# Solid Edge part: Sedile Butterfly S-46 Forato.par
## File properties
Title: SEDILE BUTTERFLY S-46 FORATA
Author: DESYS
Template: Iso Part.par
Last saved by: PIM_1
Revision: 16
Application: Solid Edge
Tipo di contenuto documento: 0
Accuracy: 0,990
Document Number: 4010
Revision: 0
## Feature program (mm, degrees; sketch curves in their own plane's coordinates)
sketch for "unnamed Protrusion 1" plane through (41.4558, 0, 41.4558) normal (0, 1, 0) x-axis (-1, 0, 0)
extrude "unnamed Protrusion 1" add finite 25 along +normal
sketch for "ScavoEstrusione_1" #1 plane through (180, 25, -217.5) normal (0, 1, 0) x-axis (1, 0, 0)
  line (-60, 177.5) -> (-60, 297.3411)
  line (-190, 297.3411) -> (-60, 297.3411)
  line (-190, 177.5) -> (-190, 297.3411)
  line (-60, 177.5) -> (-190, 177.5)
sketch for "ScavoEstrusione_1" #2 plane through (180, 25, -217.5) normal (0, 1, 0) x-axis (1, 0, 0)
  line (60, 177.5) -> (60, 297.3411)
  line (60, 297.3411) -> (190, 297.3411)
  line (190, 177.5) -> (190, 297.3411)
  line (60, 177.5) -> (190, 177.5)
extrude "ScavoEstrusione_1" cut finite 780 along -normal
sketch for "ScavoEstrusione_2" plane through (180, 25, -217.5) normal (0, 1, 0) x-axis (1, 0, 0)
  line (-75, -157.5) -> (75, -157.5)
  arc centre (75, -107.5) radius 50 from (125, -107.5) to (75, -157.5) cw
  line (125, -107.5) -> (125, 72.5)
  arc centre (75, 72.5) radius 50 from (125, 72.5) to (75, 122.5) ccw
  line (-75, 122.5) -> (75, 122.5)
  arc centre (-75, 72.5) radius 50 from (-75, 122.5) to (-125, 72.5) ccw
  line (-125, 72.5) -> (-125, -107.5)
  arc centre (-75, -107.5) radius 50 from (-75, -157.5) to (-125, -107.5) cw
extrude "ScavoEstrusione_2" cut finite 546 along -normal
sketch for "ScavoEstrusione_3" #1 plane through (180, 25, -217.5) normal (0, 1, 0) x-axis (1, 0, 0)
  arc centre (-75, 72.5) radius 55 from (-75, 127.5) to (-130, 72.5) ccw
  line (-130, 72.5) -> (-130, -107.5)
  arc centre (-75, -107.5) radius 55 from (-130, -107.5) to (-75, -162.5) ccw
  line (-75, -162.5) -> (75, -162.5)
  arc centre (75, -107.5) radius 55 from (75, -162.5) to (130, -107.5) ccw
  line (130, -107.5) -> (130, 72.5)
  arc centre (75, 72.5) radius 55 from (130, 72.5) to (75, 127.5) ccw
  line (75, 127.5) -> (-75, 127.5)
sketch for "ScavoEstrusione_3" #2 plane through (180, 25, -217.5) normal (0, 1, 0) x-axis (1, 0, 0)
  line (-175, 172.5) -> (-45, 172.5)
  line (-45, 172.5) -> (-45, 232.1356)
  line (-45, 232.1356) -> (45, 232.1356)
  line (45, 172.5) -> (45, 232.1356)
  line (175, 172.5) -> (45, 172.5)
  line (175, -212.5) -> (175, 172.5)
  line (-175, -212.5) -> (175, -212.5)
  line (-175, 172.5) -> (-175, -212.5)
extrude "ScavoEstrusione_3" cut finite 20 along -normal
fillet "Rotondo_1" radius 75
fillet "Rotondo_2" radius 80
fillet "Rotondo_3" radius 30
fillet "Rotondo_4" radius 30
fillet "Rotondo_5" radius 4
fillet "Rotondo_6" radius 4
fillet "Rotondo_7" radius 10
fillet "Rotondo_8" radius 10
fillet "Rotondo_9" radius 2
fillet "Rotondo_10" radius 2
fillet "Rotondo_11" radius 2
fillet "Rotondo_12" radius 5
fillet "Rotondo_13" radius 5
fillet "Rotondo_14" radius 5
fillet "Rotondo_15" radius 2
fillet "Rotondo_16" radius 2
fillet "Rotondo_17" radius 2
fillet "Rotondo_18" radius 2
fillet "Rotondo_19" radius 2
fillet "Rotondo_20" radius 2
fillet "Rotondo_21" radius 2
fillet "Rotondo_22" radius 2
fillet "Rotondo_23" radius 2
fillet "Rotondo_24" radius 5
fillet "Rotondo_25" radius 5
fillet "Rotondo_26" radius 5
fillet "Rotondo_28" radius 5
fillet "Rotondo_29" radius 5
sketch for "ProtrusioneEstrusa_3" #1 plane through (180, 5, -221.5) normal (0, 1, 0) x-axis (1, 0, 0)
sketch for "ProtrusioneEstrusa_3" #2 plane through (180, 5, -221.5) normal (0, 1, 0) x-axis (1, 0, 0)
sketch for "ProtrusioneEstrusa_3" #3 plane through (180, 5, -221.5) normal (0, 1, 0) x-axis (1, 0, 0)
  arc centre (150.6687, 136.7336) radius 25 from (134.7253, 117.4772) to (129.6162, 123.2505) cw
  arc centre (137.1951, 128.1044) radius 9 from (129.6162, 123.2505) to (131.1196, 134.7443) cw
  line (131.1196, 134.7443) -> (151.4535, 153.3498)
  arc centre (157.6663, 146.8382) radius 9 from (163.0227, 154.0707) to (151.4535, 153.3498) ccw
  arc centre (148.1438, 133.9805) radius 25 from (165.4262, 152.0447) to (163.0227, 154.0707) ccw
  arc centre (159.2046, 145.5416) radius 9 from (165.1443, 138.78) to (165.4262, 152.0447) ccw
  line (144.46, 119.8419) -> (165.1443, 138.78)
  arc centre (137.8276, 125.9256) radius 9 from (144.46, 119.8419) to (134.7253, 117.4772) cw
sketch for "ProtrusioneEstrusa_3" #4 plane through (180, 5, -221.5) normal (0, 1, 0) x-axis (1, 0, 0)
  arc centre (128.7376, -173.2514) radius 25 from (144.681, -192.5078) to (149.7901, -186.7345) ccw
  arc centre (142.2112, -181.8806) radius 9 from (149.7901, -186.7345) to (148.2867, -175.2407) ccw
  line (148.2867, -175.2407) -> (127.9528, -156.6352)
  arc centre (121.74, -163.1467) radius 9 from (116.3836, -155.9143) to (127.9528, -156.6352) cw
  arc centre (131.2625, -176.0045) radius 25 from (113.9801, -157.9402) to (116.3836, -155.9143) cw
  arc centre (120.2017, -164.4434) radius 9 from (114.262, -171.205) to (113.9801, -157.9402) cw
  line (134.9463, -190.1431) -> (114.262, -171.205)
  arc centre (141.5787, -184.0594) radius 9 from (134.9463, -190.1431) to (144.681, -192.5078) ccw
extrude "ProtrusioneEstrusa_3" add finite 25 along +normal
fillet "Rotondo_30" radius 2
fillet "Rotondo_31" radius 2
fillet "Rotondo_32" radius 2
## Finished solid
Body 1: solid body, 191 faces, 451 edges, 266 vertices.
  Faces by surface: cylinder 93, torus 58, plane 39, sphere 1
  Edges by curve: circle 239, line 189, intersection 21, ellipse 2
Bounding box of the edges (mm; curved faces can reach further): 360.000 x 30.000 x 435.000, from (0, 0, -435) to (360, 30, 0).
Cylindrical faces by radius (mm): R2 x27, R4 x4, R5 x20, R9 x16, R10 x2, R25 x8, R30 x4, R50 x4, R55 x4, R75 x2, R80 x2
Toroidal faces (ring radius, tube radius in mm): R2 r2 x2, R7 r2 x16, R8 r2 x2, R9 r5 x4, R23 r2 x8, R25 r5 x4, R32 r2 x2, R52 r2 x4, R53 r2 x3, R55 r5 x4, R60 r5 x4, R70 r5 x1, R75 r5 x2, R77 r2 x2
Spherical faces by radius (mm): R2 x1
Planar faces by outward normal: +x 6, +y 7, +z 5, -x 6, -y 1, -z 6, oblique 8
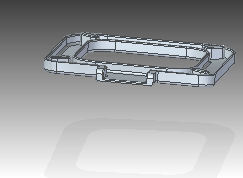
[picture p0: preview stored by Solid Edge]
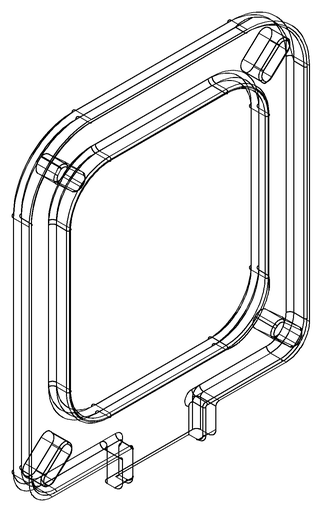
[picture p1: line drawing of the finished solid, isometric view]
